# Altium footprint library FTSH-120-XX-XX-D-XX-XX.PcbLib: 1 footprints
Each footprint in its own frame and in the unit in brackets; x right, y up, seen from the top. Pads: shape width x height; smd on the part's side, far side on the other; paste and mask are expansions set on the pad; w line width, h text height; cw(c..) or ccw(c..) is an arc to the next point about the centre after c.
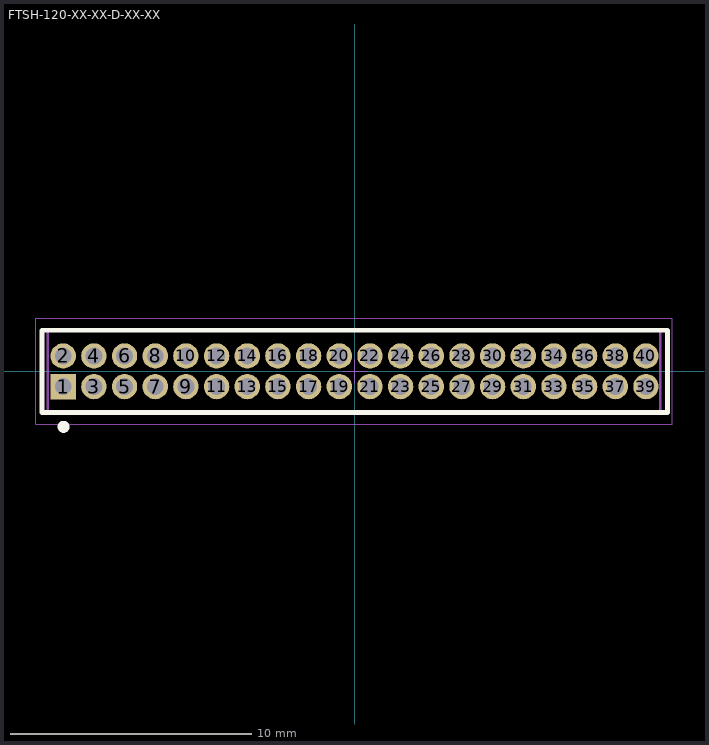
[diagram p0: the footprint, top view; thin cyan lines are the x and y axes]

## FTSH-120-XX-XX-D-XX-XX [mm] "1.27mm pitch, 40 pin, terminal strip; SMT"
height 3.05
pads (40):
  rect 1.05x1.05 / inner round 1.05 / far side rect 1.05x1.05 hole 0.7 mask+0: 1(-12.065,-0.635)
  round 1.05 hole 0.7 unplated mask+0: 2(-12.065,0.635) 3(-10.795,-0.635) 4(-10.795,0.635) 5(-9.525,-0.635) 6(-9.525,0.635) 7(-8.255,-0.635) 8(-8.255,0.635) 9(-6.985,-0.635) 10(-6.985,0.635) 11(-5.715,-0.635) 12(-5.715,0.635) 13(-4.445,-0.635) 14(-4.445,0.635) 15(-3.175,-0.635) 16(-3.175,0.635) 17(-1.905,-0.635) 18(-1.905,0.635) 19(-0.635,-0.635) 20(-0.635,0.635) 21(0.635,-0.635) 22(0.635,0.635) 23(1.905,-0.635) 24(1.905,0.635) 25(3.175,-0.635) 26(3.175,0.635) 27(4.445,-0.635) 28(4.445,0.635) 29(5.715,-0.635) 30(5.715,0.635) 31(6.985,-0.635) 32(6.985,0.635) 33(8.255,-0.635) 34(8.255,0.635) 35(9.525,-0.635) 36(9.525,0.635) 37(10.795,-0.635) 38(10.795,0.635) 39(12.065,-0.635) 40(12.065,0.635)
Top Overlay:
  circle w0.25: c-12.05,-2.3 r0.125
  lines w0.2: -12.95,-1.7 12.95,-1.7 12.95,1.7 -12.95,1.7 -12.95,-1.7
Mechanical 12:
  lines w0.001: -12.7,-1.7 12.65,-1.7 12.65,1.7 -12.7,1.7 -12.7,-1.7
Mechanical 13:
  lines w0.1: -12.7,-1.7 12.65,-1.7 12.65,1.7 -12.7,1.7 -12.7,-1.7
  text ".Designator" at 0.127,0.254 h1.52
Mechanical 15:
  lines w0.05: -0.5,0 0.5,0 ; 0,-0.5 0,0.5 ; -13.2,-2.2 13.15,-2.2 13.15,2.2 -13.2,2.2 -13.2,-2.2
